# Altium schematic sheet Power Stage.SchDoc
size 431 x 279 mm; Date: Not shown in title block; ApprovedBy: Not shown in title block; CheckedBy: Not shown in title block; Author: Not shown in title block; CompanyName: Not shown in title block; Engineer: Not shown in title block; Organization: Not shown in title block; Address1: Not shown in title block; Address2: Not shown in title block; Address3: Not shown in title block; Address4: Not shown in title block; DocumentNumber: 2; Revision: Use project parameter SCH_Rev; SheetNumber: 2; SheetTotal: 3; PageSetup: Record=PageOptions¦CenterHorizontal=True¦CenterVertical=True¦PrintScale=1.00¦XCorrection=1.00¦YCorrection=1.00¦PrintKind=0¦BorderSize=5000000¦LeftOffset=0¦BottomOffset=0¦Orientation=2¦PaperLength=1000¦PaperWidth=1000¦Scale=100¦PaperSource=15¦PrintQuality=600¦MediaType=1¦DitherType=10¦PaperKind=Letter¦PrintScaleMode=1
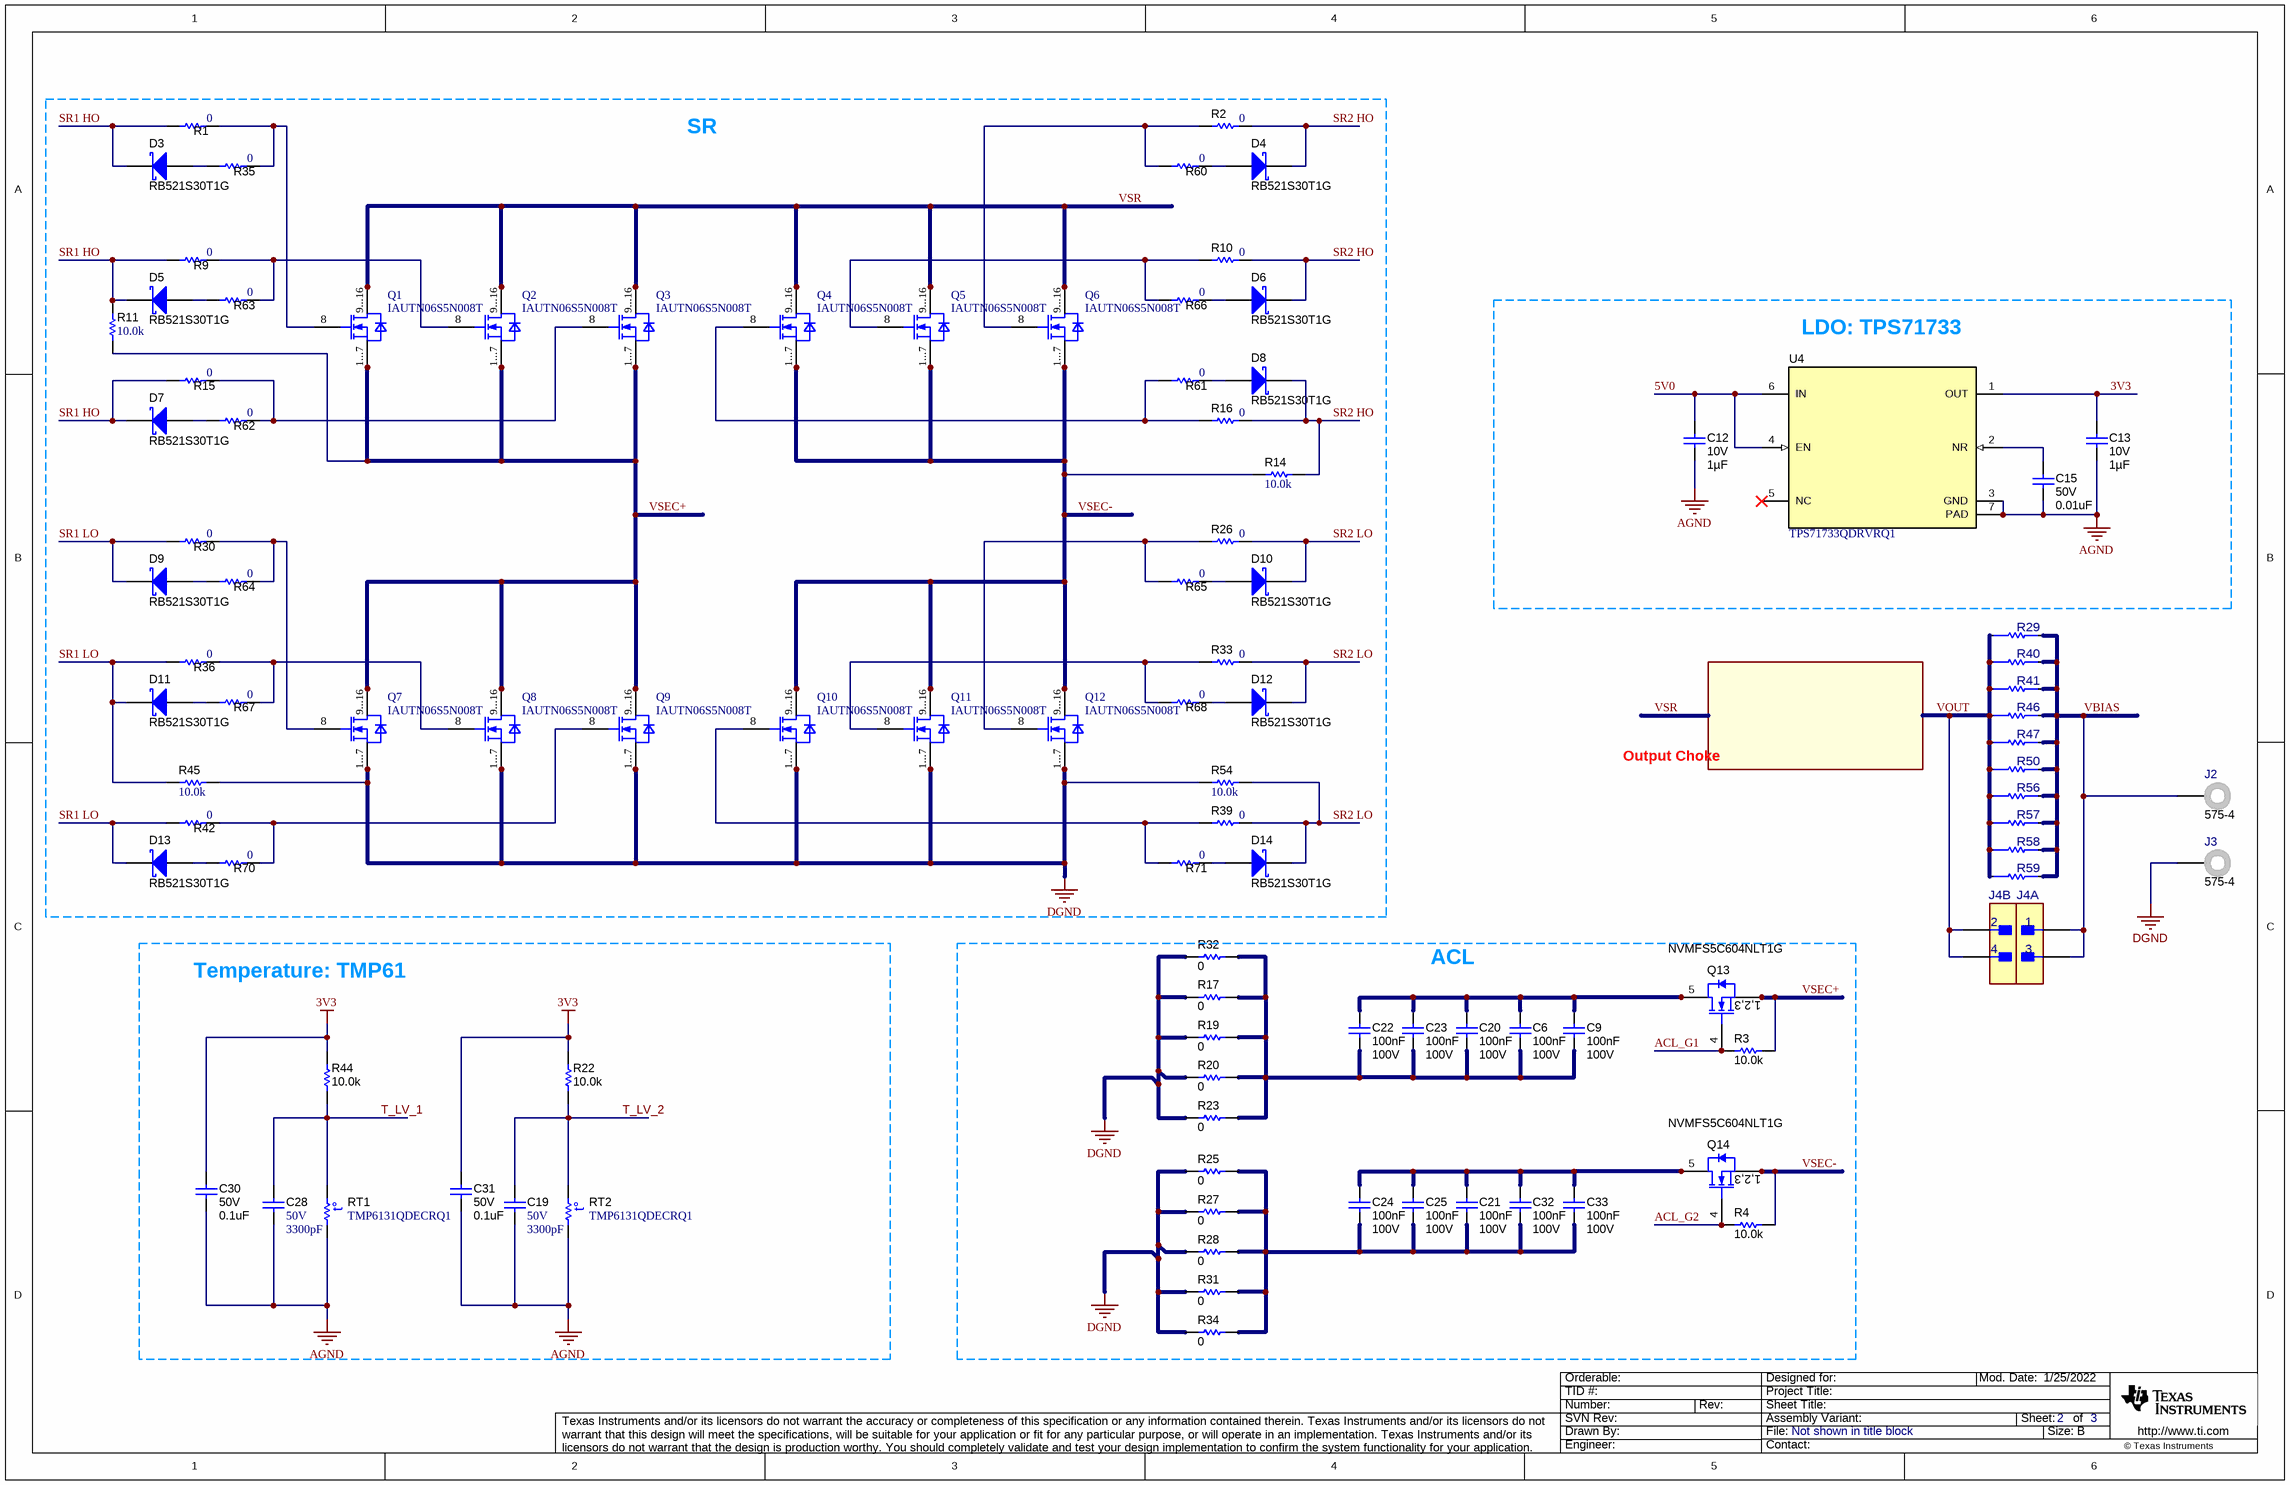
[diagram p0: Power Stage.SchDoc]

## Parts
C6  Cap_F: 100nF  VDC_V: 100V  [0805_HV]  (hidden comment: GCM21BR72A104KA37L)
C9  Cap_F: 100nF  VDC_V: 100V  [0805_HV]  (hidden comment: GCM21BR72A104KA37L)
C12  VDC_V: 10V  ValueDisplayed: 1µF  [0402]  (hidden comment: GRT155C71A105KE13D)
C13  VDC_V: 10V  ValueDisplayed: 1µF  [0402]  (hidden comment: GRT155C71A105KE13D)
C15  VDC_V: 50V  ValueDisplayed: 0.01uF  [0402]  (hidden comment: CGA2B3X7R1H103K050BB)
C19  VDC_V: 50V  ValueDisplayed: 3300pF  [0402]  (hidden comment: CGA2B2X7R1H332K050BA)
C20  Cap_F: 100nF  VDC_V: 100V  [0805_HV]  (hidden comment: GCM21BR72A104KA37L)
C21  Cap_F: 100nF  VDC_V: 100V  [0805_HV]  (hidden comment: GCM21BR72A104KA37L)
C22  Cap_F: 100nF  VDC_V: 100V  [0805_HV]  (hidden comment: GCM21BR72A104KA37L)
C23  Cap_F: 100nF  VDC_V: 100V  [0805_HV]  (hidden comment: GCM21BR72A104KA37L)
C24  Cap_F: 100nF  VDC_V: 100V  [0805_HV]  (hidden comment: GCM21BR72A104KA37L)
C25  Cap_F: 100nF  VDC_V: 100V  [0805_HV]  (hidden comment: GCM21BR72A104KA37L)
C28  VDC_V: 50V  ValueDisplayed: 3300pF  [0402]  (hidden comment: CGA2B2X7R1H332K050BA)
C30  VDC_V: 50V  ValueDisplayed: 0.1uF  [0402]  (hidden comment: GCM155R71H104KE02D)
C31  VDC_V: 50V  ValueDisplayed: 0.1uF  [0402]  (hidden comment: GCM155R71H104KE02D)
C32  Cap_F: 100nF  VDC_V: 100V  [0805_HV]  (hidden comment: GCM21BR72A104KA37L)
C33  Cap_F: 100nF  VDC_V: 100V  [0805_HV]  (hidden comment: GCM21BR72A104KA37L)
D3  RB521S30T1G  [SOD-523]
D4  RB521S30T1G  [SOD-523]
D5  RB521S30T1G  [SOD-523]
D6  RB521S30T1G  [SOD-523]
D7  RB521S30T1G  [SOD-523]
D8  RB521S30T1G  [SOD-523]
D9  RB521S30T1G  [SOD-523]
D10  RB521S30T1G  [SOD-523]
D11  RB521S30T1G  [SOD-523]
D12  RB521S30T1G  [SOD-523]
D13  RB521S30T1G  [SOD-523]
D14  RB521S30T1G  [SOD-523]
J2  575-4  [Keystone_575-4]
J3  575-4  [Keystone_575-4]
J4  FTSH-102-01-L-D-RA  [FP-FTSH-102-01-L-D-RA_HDR4-MFG]  (value not drawn)  (parts A,B of 2)
Q1  IAUTN06S5N008T  [SOIC120P1500X235-16N-1-V]
Q2  IAUTN06S5N008T  [SOIC120P1500X235-16N-1-V]
Q3  IAUTN06S5N008T  [SOIC120P1500X235-16N-1-V]
Q4  IAUTN06S5N008T  [SOIC120P1500X235-16N-1-V]
Q5  IAUTN06S5N008T  [SOIC120P1500X235-16N-1-V]
Q6  IAUTN06S5N008T  [SOIC120P1500X235-16N-1-V]
Q7  IAUTN06S5N008T  [SOIC120P1500X235-16N-1-V]
Q8  IAUTN06S5N008T  [SOIC120P1500X235-16N-1-V]
Q9  IAUTN06S5N008T  [SOIC120P1500X235-16N-1-V]
Q10  IAUTN06S5N008T  [SOIC120P1500X235-16N-1-V]
Q11  IAUTN06S5N008T  [SOIC120P1500X235-16N-1-V]
Q12  IAUTN06S5N008T  [SOIC120P1500X235-16N-1-V]
Q13  NVMFS5C604NLT1G  [TRANS_DFN5]
Q14  NVMFS5C604NLT1G  [TRANS_DFN5]
R1  ValueDisplayed: 0  [0402]  (hidden comment: CRCW04020000Z0EDHP)
R2  ValueDisplayed: 0  [0402]  (hidden comment: CRCW04020000Z0EDHP)
R3  ValueDisplayed: 10.0k  [0402]  (hidden comment: RMCF0402FT10K0)
R4  ValueDisplayed: 10.0k  [0402]  (hidden comment: RMCF0402FT10K0)
R9  ValueDisplayed: 0  [0402]  (hidden comment: CRCW04020000Z0EDHP)
R10  ValueDisplayed: 0  [0402]  (hidden comment: CRCW04020000Z0EDHP)
R11  ValueDisplayed: 10.0k  [0402]  (hidden comment: ERJPA2F1002X)
R14  ValueDisplayed: 10.0k  [0402]  (hidden comment: ERJPA2F1002X)
R15  ValueDisplayed: 0  [0402]  (hidden comment: CRCW04020000Z0EDHP)
R16  ValueDisplayed: 0  [0402]  (hidden comment: CRCW04020000Z0EDHP)
R17  ValueDisplayed: 0  [0805_HV]  (hidden comment: CRCW08050000Z0EA)
R19  ValueDisplayed: 0  [0805_HV]  (hidden comment: CRCW08050000Z0EA)
R20  ValueDisplayed: 0  [0805_HV]  (hidden comment: CRCW08050000Z0EA)
R22  ValueDisplayed: 10.0k  [0402]  (hidden comment: RMCF0402FT10K0)
R23  ValueDisplayed: 0  [0805_HV]  (hidden comment: CRCW08050000Z0EA)
R25  ValueDisplayed: 0  [0805_HV]  (hidden comment: CRCW08050000Z0EA)
R26  ValueDisplayed: 0  [0402]  (hidden comment: CRCW04020000Z0EDHP)
R27  ValueDisplayed: 0  [0805_HV]  (hidden comment: CRCW08050000Z0EA)
R28  ValueDisplayed: 0  [0805_HV]  (hidden comment: CRCW08050000Z0EA)
R29  CSSH0805FTL500  [FP-CSSH0805FTL500_0805-MFG]  (value not drawn)
R30  ValueDisplayed: 0  [0402]  (hidden comment: CRCW04020000Z0EDHP)
R31  ValueDisplayed: 0  [0805_HV]  (hidden comment: CRCW08050000Z0EA)
R32  ValueDisplayed: 0  [0805_HV]  (hidden comment: CRCW08050000Z0EA)
R33  ValueDisplayed: 0  [0402]  (hidden comment: CRCW04020000Z0EDHP)
R34  ValueDisplayed: 0  [0805_HV]  (hidden comment: CRCW08050000Z0EA)
R35  ValueDisplayed: 0  [0402]  (hidden comment: CRCW04020000Z0EDHP)
R36  ValueDisplayed: 0  [0402]  (hidden comment: CRCW04020000Z0EDHP)
R39  ValueDisplayed: 0  [0402]  (hidden comment: CRCW04020000Z0EDHP)
R40  CSSH0805FTL500  [FP-CSSH0805FTL500_0805-MFG]  (value not drawn)
R41  CSSH0805FTL500  [FP-CSSH0805FTL500_0805-MFG]  (value not drawn)
R42  ValueDisplayed: 0  [0402]  (hidden comment: CRCW04020000Z0EDHP)
R44  ValueDisplayed: 10.0k  [0402]  (hidden comment: RMCF0402FT10K0)
R45  ValueDisplayed: 10.0k  [0402]  (hidden comment: ERJPA2F1002X)
R46  CSSH0805FTL500  [FP-CSSH0805FTL500_0805-MFG]  (value not drawn)
R47  CSSH0805FTL500  [FP-CSSH0805FTL500_0805-MFG]  (value not drawn)
R50  CSSH0805FTL500  [FP-CSSH0805FTL500_0805-MFG]  (value not drawn)
R54  ValueDisplayed: 10.0k  [0402]  (hidden comment: ERJPA2F1002X)
R56  CSSH0805FTL500  [FP-CSSH0805FTL500_0805-MFG]  (value not drawn)
R57  CSSH0805FTL500  [FP-CSSH0805FTL500_0805-MFG]  (value not drawn)
R58  CSSH0805FTL500  [FP-CSSH0805FTL500_0805-MFG]  (value not drawn)
R59  CSSH0805FTL500  [FP-CSSH0805FTL500_0805-MFG]  (value not drawn)
R60  ValueDisplayed: 0  [0402]  (hidden comment: CRCW04020000Z0EDHP)
R61  ValueDisplayed: 0  [0402]  (hidden comment: CRCW04020000Z0EDHP)
R62  ValueDisplayed: 0  [0402]  (hidden comment: CRCW04020000Z0EDHP)
R63  ValueDisplayed: 0  [0402]  (hidden comment: CRCW04020000Z0EDHP)
R64  ValueDisplayed: 0  [0402]  (hidden comment: CRCW04020000Z0EDHP)
R65  ValueDisplayed: 0  [0402]  (hidden comment: CRCW04020000Z0EDHP)
R66  ValueDisplayed: 0  [0402]  (hidden comment: CRCW04020000Z0EDHP)
R67  ValueDisplayed: 0  [0402]  (hidden comment: CRCW04020000Z0EDHP)
R68  ValueDisplayed: 0  [0402]  (hidden comment: CRCW04020000Z0EDHP)
R70  ValueDisplayed: 0  [0402]  (hidden comment: CRCW04020000Z0EDHP)
R71  ValueDisplayed: 0  [0402]  (hidden comment: CRCW04020000Z0EDHP)
RT1  TMP6131QDECRQ1  [DEC0002A-MFG]
RT2  TMP6131QDECRQ1  [DEC0002A-MFG]
U4  TPS71733QDRVRQ1  [DRV0006A]

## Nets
3V3: C13.1 C30.1 C31.1 R22.2 R44.2 U4.1(OUT)
AGND: C12.2 C13.2 C15.2 C19.2 C28.2 C30.2 C31.2 RT1.1 RT2.1 U4.3(GND) U4.7(PAD)
DGND: J3.1 Q7.1(SOURCE1) Q7.2(SOURCE2) Q7.3(SOURCE3) Q7.4(SOURCE4) Q7.5(SOURCE5) Q7.6(SOURCE6) Q7.7(SOURCE7) Q8.1(SOURCE1) Q8.2(SOURCE2) Q8.3(SOURCE3) Q8.4(SOURCE4) Q8.5(SOURCE5) Q8.6(SOURCE6) Q8.7(SOURCE7) Q9.1(SOURCE1) Q9.2(SOURCE2) Q9.3(SOURCE3) Q9.4(SOURCE4) Q9.5(SOURCE5) Q9.6(SOURCE6) Q9.7(SOURCE7) Q10.1(SOURCE1) Q10.2(SOURCE2) Q10.3(SOURCE3) Q10.4(SOURCE4) Q10.5(SOURCE5) Q10.6(SOURCE6) Q10.7(SOURCE7) Q11.1(SOURCE1) Q11.2(SOURCE2) Q11.3(SOURCE3) Q11.4(SOURCE4) Q11.5(SOURCE5) Q11.6(SOURCE6) Q11.7(SOURCE7) Q12.1(SOURCE1) Q12.2(SOURCE2) Q12.3(SOURCE3) Q12.4(SOURCE4) Q12.5(SOURCE5) Q12.6(SOURCE6) Q12.7(SOURCE7) R17.1 R19.1 R20.1 R23.1 R25.1 R27.1 R28.1 R31.1 R32.1 R34.1 R45.1 R54.2
5V0: C12.1 U4.4(EN) U4.6(IN)
ACL_G1: Q13.4(G) R3.2
ACL_G2: Q14.4(G) R4.2
SR1 HO: D3.1(K) D5.1(K) D7.1(K) R1.1 R9.1 R11.2 R15.1
SR1 LO: D9.1(K) D11.1(K) D13.1(K) R30.1 R36.1 R42.1 R45.2
SR2 HO: D4.1(K) D6.1(K) D8.1(K) R2.2 R10.2 R14.1 R16.2
SR2 LO: D10.1(K) D12.1(K) D14.1(K) R26.2 R33.2 R39.2 R54.1
T_LV_1: C28.1 R44.1 RT1.2
T_LV_2: C19.1 R22.1 RT2.2
VBIAS: J2.1 J4.1 J4.3 R29.2 R40.2 R41.2 R46.2 R47.2 R50.2 R56.2 R57.2 R58.2 R59.2
VOUT: J4.2 J4.4 R29.1 R40.1 R41.1 R46.1 R47.1 R50.1 R56.1 R57.1 R58.1 R59.1
VSEC+: Q1.1(SOURCE1) Q1.2(SOURCE2) Q1.3(SOURCE3) Q1.4(SOURCE4) Q1.5(SOURCE5) Q1.6(SOURCE6) Q1.7(SOURCE7) Q2.1(SOURCE1) Q2.2(SOURCE2) Q2.3(SOURCE3) Q2.4(SOURCE4) Q2.5(SOURCE5) Q2.6(SOURCE6) Q2.7(SOURCE7) Q3.1(SOURCE1) Q3.2(SOURCE2) Q3.3(SOURCE3) Q3.4(SOURCE4) Q3.5(SOURCE5) Q3.6(SOURCE6) Q3.7(SOURCE7) Q7.9(DRAIN1) Q7.10(DRAIN2) Q7.11(DRAIN3) Q7.12(DRAIN4) Q7.13(DRAIN5) Q7.14(DRAIN6) Q7.15(DRAIN7) Q7.16(DRAIN8) Q8.9(DRAIN1) Q8.10(DRAIN2) Q8.11(DRAIN3) Q8.12(DRAIN4) Q8.13(DRAIN5) Q8.14(DRAIN6) Q8.15(DRAIN7) Q8.16(DRAIN8) Q9.9(DRAIN1) Q9.10(DRAIN2) Q9.11(DRAIN3) Q9.12(DRAIN4) Q9.13(DRAIN5) Q9.14(DRAIN6) Q9.15(DRAIN7) Q9.16(DRAIN8) Q13.1(S) Q13.2(S) Q13.3(S) R3.1 R11.1
VSEC-: Q4.1(SOURCE1) Q4.2(SOURCE2) Q4.3(SOURCE3) Q4.4(SOURCE4) Q4.5(SOURCE5) Q4.6(SOURCE6) Q4.7(SOURCE7) Q5.1(SOURCE1) Q5.2(SOURCE2) Q5.3(SOURCE3) Q5.4(SOURCE4) Q5.5(SOURCE5) Q5.6(SOURCE6) Q5.7(SOURCE7) Q6.1(SOURCE1) Q6.2(SOURCE2) Q6.3(SOURCE3) Q6.4(SOURCE4) Q6.5(SOURCE5) Q6.6(SOURCE6) Q6.7(SOURCE7) Q10.9(DRAIN1) Q10.10(DRAIN2) Q10.11(DRAIN3) Q10.12(DRAIN4) Q10.13(DRAIN5) Q10.14(DRAIN6) Q10.15(DRAIN7) Q10.16(DRAIN8) Q11.9(DRAIN1) Q11.10(DRAIN2) Q11.11(DRAIN3) Q11.12(DRAIN4) Q11.13(DRAIN5) Q11.14(DRAIN6) Q11.15(DRAIN7) Q11.16(DRAIN8) Q12.9(DRAIN1) Q12.10(DRAIN2) Q12.11(DRAIN3) Q12.12(DRAIN4) Q12.13(DRAIN5) Q12.14(DRAIN6) Q12.15(DRAIN7) Q12.16(DRAIN8) Q14.1(S) Q14.2(S) Q14.3(S) R4.1 R14.2
VSR: Q1.9(DRAIN1) Q1.10(DRAIN2) Q1.11(DRAIN3) Q1.12(DRAIN4) Q1.13(DRAIN5) Q1.14(DRAIN6) Q1.15(DRAIN7) Q1.16(DRAIN8) Q2.9(DRAIN1) Q2.10(DRAIN2) Q2.11(DRAIN3) Q2.12(DRAIN4) Q2.13(DRAIN5) Q2.14(DRAIN6) Q2.15(DRAIN7) Q2.16(DRAIN8) Q3.9(DRAIN1) Q3.10(DRAIN2) Q3.11(DRAIN3) Q3.12(DRAIN4) Q3.13(DRAIN5) Q3.14(DRAIN6) Q3.15(DRAIN7) Q3.16(DRAIN8) Q4.9(DRAIN1) Q4.10(DRAIN2) Q4.11(DRAIN3) Q4.12(DRAIN4) Q4.13(DRAIN5) Q4.14(DRAIN6) Q4.15(DRAIN7) Q4.16(DRAIN8) Q5.9(DRAIN1) Q5.10(DRAIN2) Q5.11(DRAIN3) Q5.12(DRAIN4) Q5.13(DRAIN5) Q5.14(DRAIN6) Q5.15(DRAIN7) Q5.16(DRAIN8) Q6.9(DRAIN1) Q6.10(DRAIN2) Q6.11(DRAIN3) Q6.12(DRAIN4) Q6.13(DRAIN5) Q6.14(DRAIN6) Q6.15(DRAIN7) Q6.16(DRAIN8)
NetC6_1: C6.1 C9.1 C20.1 C22.1 C23.1 Q13.5(D) Q13.6(D)
NetC6_2: C6.2 C9.2 C20.2 C22.2 C23.2 R17.2 R19.2 R20.2 R23.2 R32.2
NetC15_1: C15.1 U4.2(NR)
NetC21_1: C21.1 C24.1 C25.1 C32.1 C33.1 Q14.5(D) Q14.6(D)
NetC21_2: C21.2 C24.2 C25.2 C32.2 C33.2 R25.2 R27.2 R28.2 R31.2 R34.2
NetD3_2: D3.2(A) R35.1
NetD4_2: D4.2(A) R60.2
NetD5_2: D5.2(A) R63.1
NetD6_2: D6.2(A) R66.2
NetD7_2: D7.2(A) R62.1
NetD8_2: D8.2(A) R61.2
NetD9_2: D9.2(A) R64.1
NetD10_2: D10.2(A) R65.2
NetD11_2: D11.2(A) R67.1
NetD12_2: D12.2(A) R68.2
NetD13_2: D13.2(A) R70.1
NetD14_2: D14.2(A) R71.2
NetQ1_8: Q1.8(GATE) R1.2 R35.2
NetQ2_8: Q2.8(GATE) R9.2 R63.2
NetQ3_8: Q3.8(GATE) R15.2 R62.2
NetQ4_8: Q4.8(GATE) R16.1 R61.1
NetQ5_8: Q5.8(GATE) R10.1 R66.1
NetQ6_8: Q6.8(GATE) R2.1 R60.1
NetQ7_8: Q7.8(GATE) R30.2 R64.2
NetQ8_8: Q8.8(GATE) R36.2 R67.2
NetQ9_8: Q9.8(GATE) R42.2 R70.2
NetQ10_8: Q10.8(GATE) R39.1 R71.1
NetQ11_8: Q11.8(GATE) R33.1 R68.1
NetQ12_8: Q12.8(GATE) R26.1 R65.1

Not connected (* = marked no-connect by the designer): U4 5(NC)*

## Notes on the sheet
- SR
- LDO: TPS71733
- Output Choke
- Temperature: TMP61
- ACL

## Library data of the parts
C6 C9 C20-C25 C32 C33 = CMP-0860440-1: CAP, CERM, 0.1 µF, 100 V,+/- 10%, X7R, AEC-Q200 Grade 1, 0805; Manufacturer: MuRata; SizeY_mm: 1.25; ValueDisplayed: 0.1µF; SizeX_mm: 2; Cap_Case: 0805; AEC Grade: 1; Polarized: N; Value: 0.1uF; TaMin_C: -55°C; SizeZ_mm: 1.45; TaMax_C: 125°C; U/M: EA; SizeArea_mm2: 2.5; AEC Qualified: Y; SizeAreaWB_mm2: 6.75; AEC Category: Q200
C12 C13 = CMP-0085818-1: CAP, CERM, 1 µF, 10 V,+/- 10%, X7S, AEC-Q200 Grade 1, 0402; Manufacturer: MuRata; Value: 1uF; SizeX_mm: 1; TaMax_C: 125°C; SizeArea_mm2: 0.5; SizeZ_mm: 0.6; AEC Category: Q200; Polarized: N; SizeAreaWB_mm2: 3; TaMin_C: -55°C; AEC Qualified: Y; U/M: EA
C15 = CMP-0006324-2: CAP, CERM, 0.01 uF, 50 V, +/- 10%, X7R, AEC-Q200 Grade 1, 0402; Manufacturer: TDK; TaMin_C: -55°C; ESR_ohm: 0.3331; Polarized: N; SizeAreaWB_mm2: 3; Value1: 0.333065 ohm; U/M: EA; Value: 0.01uF; TaMax_C: 125°C; SizeZ_mm: 0.6; SizeX_mm: 1; SizeY_mm: 0.5; AEC Qualified: Y; Cap_F: 10nF; IRMS_A: 323.373mA; AEC Category: Q200
C19 C28 = CMP-0006319-2: CAP, CERM, 3300 pF, 50 V, +/- 10%, X7R, AEC-Q200 Grade 1, 0402; Manufacturer: TDK; TaMin_C: -55°C; ESR_ohm: 7.85178d; Polarized: N; SizeAreaWB_mm2: 3; Value1: 0.785178 ohm; U/M: EA; Value: 3300pF; TaMax_C: 125°C; SizeZ_mm: 0.6; SizeX_mm: 1; SizeY_mm: 0.5; AEC Qualified: Y; Cap_F: 3.3nF; IRMS_A: 2.72902dA; AEC Category: Q200
C30 C31 = CMP-0006356-1: CAP, CERM, 0.1 uF, 50 V, +/- 10%, X7R, AEC-Q200 Grade 1, 0402; Manufacturer: MuRata; TaMin_C: -55°C; Polarized: N; SizeAreaWB_mm2: 3; Value1: Unknown; U/M: EA; Value: 0.1uF; TaMax_C: 125°C; SizeZ_mm: 0.6; SizeX_mm: 1; SizeY_mm: 0.5; AEC Qualified: Y; Cap_F: 100nF; AEC Category: Q200
D3-D14 = CMP-0028768-3: Diode, Schottky, 30 V, 0.2 A, AEC-Q101, SOD-523; Manufacturer: ON Semiconductor; SizeArea_mm2: 1.53; Vr_V: 30V; Green_Lifecycle: Not Set; Value2: 0.5V; Value1: 0.2A; AEC Qualified: Y; SizeY_mm: 0.9; AEC Category: Q101; SizeZ_mm: 0.65; Vf_V: 500mV; Io_A: 200mA; Green_REACh: Incomplete; SizeAreaWB_mm2: 5.13; TJmax_C: 125°C; Value: 30V; SizeX_mm: 1.7
J2 J3 = CMP-0055165-2: Standard Banana Jack, Uninsulated, 5.5mm; Manufacturer: Keystone; CT: TRUE; Green_REACh: Passed; CNHeader: FALSE; Green_Lifecycle: Active
J4 = CMP-0120912-1: Connector Unshrouded Header HDR 4 POS 1.27mm Solder RA Thru-Hole; Manufacturer: Samtec; ContactFinish: Gold,Nickel; Current_A: 3.4A; Row_Count: 2; AEC Qualified: No; Conn Gender: Male; Conn Orientation: Right Angle; SizeZ_mm: 3.56mm
Q1-Q12 = IAUTN06S5N008T: Insulated-Gate Field-Effect Transistor (IGFET), N-Channel, Enhancement, Body Diode, Pin 1 Source, 2 Source, 3 Source , 4 Source, 5 Source, 6 Source, 7 Source, 8 Gate, 9 Drain, 10 Drain, 11 Drain, 12 Drain, 13 Drain, 14 Drain, 15 Drain, 16 Drain, 16 Pins; Manufacturer: Infineon Technologies
Q13 Q14 = CMP-0077633-1: MOSFET, N-CH, 60 V, 287 A, AEC-Q101, DFN5 5x6mm; Manufacturer: ON Semiconductor; Alternate Manufacturer: None; ChType: N; QgTyp_nC: 52.0; SizeAreaWB_mm2: 58.2725; SizeArea_mm2: 31.6725; IdsMax_A: 287A; AEC Qualified: Y; VdsMax_V: 60V; Rdson45_ohm: 1.7m; Vgs_V: 20V; AEC Category: Q101; Value: 60V; SizeZ_mm: 1.0; SizeY_mm: 6.15; Value2: 52 nC; U/M: EA; Value1: 0.0017 ohm; SizeX_mm: 5.15
R1 R2 R9 R10 R15 R16 R26 R30 R33 R35 R36 R39 R42 R60-R68 R70 R71 = CMP-0081856-1: RES, 0, 0%, 0.2 W, AEC-Q200 Grade 0, 0402; Manufacturer: Vishay-Dale; SizeAreaWB_mm2: 3; SizeArea_mm2: 0.5; AEC Qualified: Y; AEC Category: Q200; Value: 0; SizeZ_mm: 0.6; Power_W: 200mW; VDC_V: 50V; Value2: 0.2W; SizeX_mm: 1
R3 R4 R22 R44 = CMP-0026754-1: RES, 10.0 k, 1%, 0.063 W, AEC-Q200 Grade 0, 0402; Manufacturer: Stackpole Electronics Inc; Power_W: 63mW; TempCo: 100 ppm/C; Value_Code: 10k0; U/M: EA; Value: 10.0k; EIA_Code: E96; Res_ohm: 10k; SizeX_mm: 1; SizeY_mm: 0.5; SizeZ_mm: 0.6; Value2: 0.063W; AEC Qualified: Y; VDC_V: 50V; AEC Grade: 0; AEC Category: Q200
R11 R14 R45 R54 = CMP-0078779-1: RES, 10.0 k, 1%, 0.2 W, AEC-Q200 Grade 0, 0402; Manufacturer: Panasonic; Value_Code: 10k0; SizeArea_mm2: 0.5; AEC Qualified: Y; AEC Category: Q200; Res_ohm: 10k; Value: 10.0k; SizeZ_mm: 0.6; EIA_Code: E96; TempCo: 100 ppm/C; AEC Grade: 0; Power_W: 200mW; VDC_V: 50V; Value2: 0.2W; SizeX_mm: 1
R17 R19 R20 R23 R25 R27 R28 R31 R32 R34 = CMP-0020442-3: RES, 0, 5%, 0.125 W, AEC-Q200 Grade 0, 0805; Manufacturer: Vishay-Dale; Power_W: 125mW; TempCo: 200 ppm/C; Value_Code: 0000; Value: 0; EIA_Code: E24; SizeX_mm: 2; SizeY_mm: 1.25; SizeZ_mm: 1.45; Value2: 0.125W; SizeArea_mm2: 2.5; AEC Qualified: Y; VDC_V: 150V; AEC Category: Q200
R29 R40 R41 R46 R47 R50 R56-R59 = CMP-0093189-1: 500 µOhms ±1% 1W Chip Resistor 0805 (2012 Metric) Automotive AEC-Q200, Current Sense Metal Element; Manufacturer: Stackpole Electronics; AEC Qualified: Yes; SizeZ_mm: 0.8mm; TempCo: 100ppm/°C; AEC Grade: Grade 0; Res_ohm: 500µ; Value: 500µ
RT1 RT2 = CMP-0120064-2: Automotive ±1% tolerance 10kΩ linear thermistor available in an 0402 package option 2-X1SON -40 to 125; Manufacturer: Texas Instruments; SizeZ_mm: 0.5mm; AEC Qualified: Yes; AEC Grade: Grade 1; Standoff Height: 0mm; TaMax_C: +125°C; TaMin_C: -40°C; AEC Category: Q200; CompType: IC
U4 = CMP-0082417-1: Low Noise, High-Bandwidth PSRR Low-Dropout 150mA Linear Regulator for Automotive Applications, DRV0006A (WSON-6); Alternate Manufacturer: Texas Instruments; SizeAreaWB_mm2: 9; SizeZ_mm: 0.8; SizeX_mm: 2; SizeArea_mm2: 4; CompType: IC; AEC Qualified: Y; AEC Category: Q200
